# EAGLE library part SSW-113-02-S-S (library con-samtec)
THROUGH-HOLE .025" SQ POST SOCKET Source: Samtec SSW.pdf
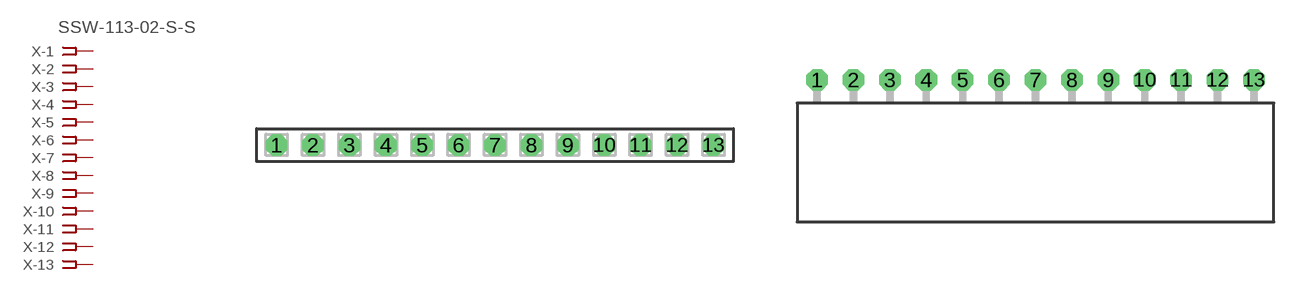
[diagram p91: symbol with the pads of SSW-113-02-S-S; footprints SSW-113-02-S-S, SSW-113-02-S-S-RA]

Designator prefix X; gates -1=FPINV -2=FPIN -3=FPIN -4=FPIN -5=FPIN -6=FPIN -7=FPIN -8=FPIN -9=FPIN -10=FPIN -11=FPIN -12=FPIN -13=FPIN

## SSW-113-02-S-S (MPN: SSW-113-02-S-S; OC_FARNELL: unknown; OC_NEWARK: 11P9532)  [SSW-113-02-S-S]
1  -1:1  pas
2  -2:1  pas
3  -3:1  pas
4  -4:1  pas
5  -5:1  pas
6  -6:1  pas
7  -7:1  pas
8  -8:1  pas
9  -9:1  pas
10  -10:1  pas
11  -11:1  pas
12  -12:1  pas
13  -13:1  pas

## SSW-113-02-S-S-RA (MPN: SSW-113-02-S-S-RA; OC_FARNELL: unknown; OC_NEWARK: 11P9533)  [SSW-113-02-S-S-RA]
Pads as for SSW-113-02-S-S

## Footprint SSW-113-02-S-S (pad centres in mm)
THROUGH-HOLE .025" SQ POST SOCKET Source: Samtec SSW.pdf
drill 1 pad 1.5 octagon: 1 -15.24,0; 2 -12.7,0; 3 -10.16,0; 4 -7.62,0; 5 -5.08,0; 6 -2.54,0; 7 0,0; 8 2.54,0; 9 5.08,0; 10 7.62,0; 11 10.16,0; 12 12.7,0; 13 15.24,0

## Footprint SSW-113-02-S-S-RA (pad centres in mm)
THROUGH-HOLE .025" SQ POST SOCKET Source: Samtec SSW.pdf
drill 1 pad 1.5 octagon: 1 -15.24,1.524; 2 -12.7,1.524; 3 -10.16,1.524; 4 -7.62,1.524; 5 -5.08,1.524; 6 -2.54,1.524; 7 0,1.524; 8 2.54,1.524; 9 5.08,1.524; 10 7.62,1.524; 11 10.16,1.524; 12 12.7,1.524; 13 15.24,1.524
